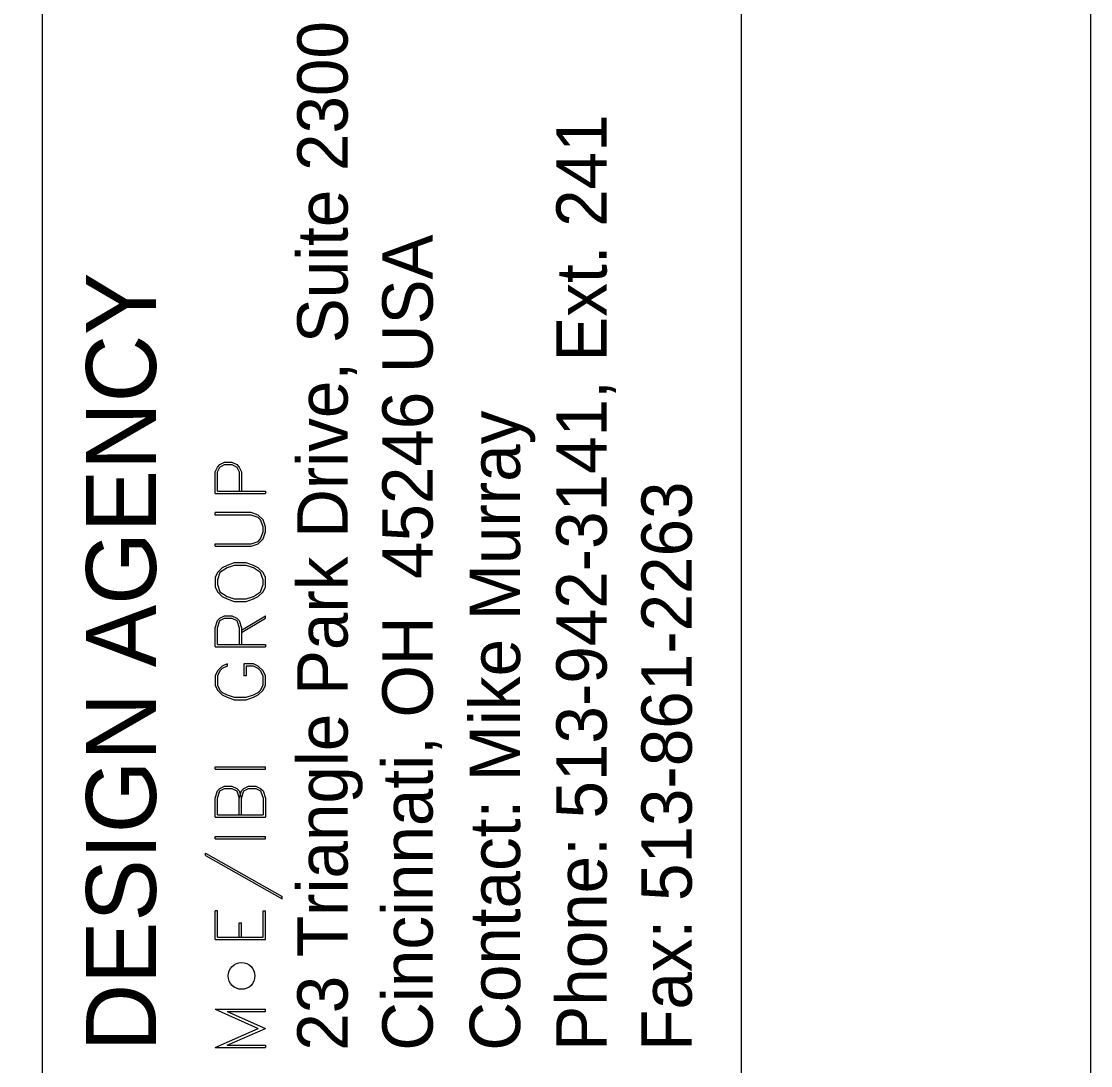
# Model space of a CAD drawing. Extents: x -1300 to 1299, y -770 to 1120.
# Drawn here: x -581.83 to -566.53, y 435.1 to 450.04 of the extents above; entities that cross this region are included whole.
import ezdxf

# ---------------------------------------------------------------- set-up
doc = ezdxf.new("R2010")
doc.units = 0
for name, color, linetype in [('SH_Border', 7, 'Continuous'), ('SH_Cut_Line', 7, 'Continuous'), ('SH_Data', 7, 'Continuous')]:
    doc.layers.add(name, color=color, linetype=linetype)

msp = doc.modelspace()

# ---------------------------------------------------------------- linework, layer by layer
at = {"layer": 'SH_Border'}
msp.add_line((-581.526, 248.063), (-581.526, 458.063), dxfattribs=at)
msp.add_lwpolyline([(-886.526, 458.063), (-571.526, 458.063), (-571.526, 248.063), (-886.526, 248.063)], close=True, dxfattribs=at)
at = {"layer": 'SH_Cut_Line'}
msp.add_lwpolyline([(-906.526, 463.063), (-566.526, 463.063), (-566.526, 243.063), (-906.526, 243.063)], close=True, dxfattribs=at)
at = {"layer": 'SH_Data'}
for p, q in [((-579.055, 443.286), (-578.334, 443.286)), ((-578.678, 441.329), (-578.334, 441.535)), ((-579.055, 441.089), (-578.334, 441.089)), ((-579.021, 438.686), (-578.369, 438.686)), ((-579.055, 438.651), (-578.334, 438.651)), ((-579.055, 436.901), (-579.055, 437.313)), ((-578.334, 436.901), (-578.334, 437.313)), ((-578.678, 436.935), (-578.678, 437.141)), ((-579.055, 436.901), (-578.334, 436.901)), ((-579.021, 436.935), (-578.369, 436.935)), ((-579.055, 435.905), (-578.437, 435.63)), ((-579.055, 435.905), (-578.334, 435.905)), ((-578.884, 435.871), (-578.334, 435.63)), ((-579.055, 435.356), (-578.437, 435.63)), ((-578.884, 435.39), (-578.334, 435.63)), ((-579.055, 435.356), (-578.334, 435.356))]:
    msp.add_line(p, q, dxfattribs=at)
for points in [[(-579.055, 443.286), (-579.055, 443.595), (-579.021, 443.664), (-578.987, 443.698), (-578.918, 443.732), (-578.815, 443.732), (-578.746, 443.698), (-578.712, 443.664), (-578.678, 443.595), (-578.678, 443.32)], [(-579.021, 443.32), (-579.021, 443.595), (-578.987, 443.664), (-578.918, 443.698), (-578.815, 443.698), (-578.746, 443.664), (-578.712, 443.595), (-578.712, 443.32)], [(-579.021, 443.32), (-578.334, 443.32), (-578.334, 443.286)], [(-579.055, 442.531), (-578.54, 442.531), (-578.437, 442.565), (-578.369, 442.634), (-578.334, 442.737), (-578.334, 442.806), (-578.369, 442.909), (-578.437, 442.977), (-578.54, 443.011), (-579.055, 443.011)], [(-579.055, 442.531), (-579.055, 442.565), (-578.54, 442.565), (-578.437, 442.6), (-578.403, 442.634), (-578.369, 442.737), (-578.369, 442.806), (-578.403, 442.909), (-578.437, 442.943), (-578.54, 442.977), (-579.055, 442.977), (-579.055, 443.011)], [(-579.055, 441.947), (-579.021, 441.879), (-578.952, 441.81), (-578.884, 441.776), (-578.781, 441.741), (-578.609, 441.741), (-578.506, 441.776), (-578.437, 441.81), (-578.369, 441.879), (-578.334, 441.947), (-578.334, 442.085), (-578.369, 442.153), (-578.437, 442.222), (-578.506, 442.256), (-578.609, 442.291), (-578.781, 442.291), (-578.884, 442.256), (-578.952, 442.222), (-579.021, 442.153), (-579.055, 442.085), (-579.055, 441.947)], [(-579.021, 441.982), (-578.987, 441.879), (-578.884, 441.81), (-578.781, 441.776), (-578.609, 441.776), (-578.506, 441.81), (-578.403, 441.879), (-578.369, 441.982), (-578.369, 442.05), (-578.403, 442.153), (-578.506, 442.222), (-578.609, 442.256), (-578.781, 442.256), (-578.884, 442.222), (-578.987, 442.153), (-579.021, 442.05), (-579.021, 441.982)], [(-579.055, 441.089), (-579.055, 441.364), (-579.021, 441.467), (-578.987, 441.501), (-578.918, 441.535), (-578.815, 441.535), (-578.746, 441.501), (-578.712, 441.467), (-578.678, 441.364), (-578.678, 441.123)], [(-579.021, 441.123), (-579.021, 441.364), (-578.987, 441.467), (-578.918, 441.501), (-578.815, 441.501), (-578.746, 441.467), (-578.712, 441.364), (-578.712, 441.123)], [(-578.678, 441.295), (-578.334, 441.501), (-578.334, 441.535)], [(-579.021, 441.123), (-578.334, 441.123), (-578.334, 441.089)], [(-578.884, 440.849), (-578.952, 440.814), (-579.021, 440.746), (-579.055, 440.677), (-579.055, 440.54), (-579.021, 440.471), (-578.952, 440.402), (-578.884, 440.368), (-578.781, 440.334), (-578.609, 440.334), (-578.506, 440.368), (-578.437, 440.402), (-578.369, 440.471), (-578.334, 440.54), (-578.334, 440.677), (-578.369, 440.746), (-578.437, 440.814), (-578.506, 440.849), (-578.643, 440.849), (-578.643, 440.677)], [(-578.884, 440.849), (-578.884, 440.814), (-578.952, 440.78), (-578.987, 440.746), (-579.021, 440.677), (-579.021, 440.54), (-578.987, 440.471), (-578.952, 440.437), (-578.884, 440.402), (-578.781, 440.368), (-578.609, 440.368), (-578.506, 440.402), (-578.437, 440.437), (-578.403, 440.471), (-578.369, 440.54), (-578.369, 440.677), (-578.403, 440.746), (-578.437, 440.78), (-578.506, 440.814), (-578.609, 440.814), (-578.609, 440.677), (-578.643, 440.677)], [(-579.055, 439.338), (-578.334, 439.338), (-578.334, 439.372)], [(-579.055, 439.338), (-579.055, 439.372), (-578.334, 439.372)], [(-579.055, 438.651), (-579.055, 438.926), (-579.021, 439.029), (-578.987, 439.063), (-578.918, 439.098), (-578.815, 439.098), (-578.746, 439.063), (-578.712, 439.029), (-578.678, 438.926)], [(-579.021, 438.686), (-579.021, 438.926), (-578.987, 439.029), (-578.918, 439.063), (-578.815, 439.063), (-578.746, 439.029), (-578.712, 438.926)], [(-578.712, 438.686), (-578.712, 438.926), (-578.678, 439.029), (-578.643, 439.063), (-578.575, 439.098), (-578.472, 439.098), (-578.403, 439.063), (-578.369, 439.029), (-578.334, 438.926), (-578.334, 438.651)], [(-578.678, 438.686), (-578.678, 438.926), (-578.643, 439.029), (-578.575, 439.063), (-578.472, 439.063), (-578.403, 439.029), (-578.369, 438.926), (-578.369, 438.686)], [(-579.055, 438.343), (-578.334, 438.343), (-578.334, 438.377)], [(-579.055, 438.343), (-579.055, 438.377), (-578.334, 438.377)], [(-579.193, 438.102), (-579.193, 438.137), (-578.094, 437.519)], [(-579.193, 438.102), (-578.094, 437.484), (-578.094, 437.519)], [(-579.021, 436.935), (-579.021, 437.313), (-579.055, 437.313)], [(-578.369, 436.935), (-578.369, 437.313), (-578.334, 437.313)], [(-578.712, 436.935), (-578.712, 437.141), (-578.678, 437.141)], [(-578.884, 435.871), (-578.334, 435.871), (-578.334, 435.905)], [(-578.884, 435.39), (-578.334, 435.39), (-578.334, 435.356)]]:
    msp.add_lwpolyline(points, dxfattribs=at)
msp.add_circle((-578.676, 436.38), 0.191, dxfattribs=at)

# ---------------------------------------------------------------- texts
for s, height, p in [('23 Triangle Park Drive, Suite 2300', 0.72094, (-577.158, 435.31)), ('Phone: 513-942-3141, Ext. 241', 0.72094, (-573.451, 435.31)), ('Cincinnati, OH  45246 USA', 0.72094, (-575.941, 435.31)), ('DESIGN AGENCY', 1.00002, (-579.901, 435.301)), ('Contact: Mike Murray', 0.72094, (-574.69, 435.31)), ('Fax: 513-861-2263', 0.72094, (-572.233, 435.31))]:
    msp.add_text(s, height=height, rotation=90, dxfattribs=at).set_placement(p)

doc.saveas('drawing.dxf')
